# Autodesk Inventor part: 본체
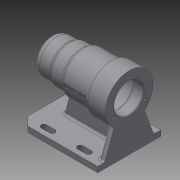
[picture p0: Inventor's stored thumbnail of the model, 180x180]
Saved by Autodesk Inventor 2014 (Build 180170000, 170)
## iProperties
Created: 2017-09
Part Number: 본체
Material: Generic
Document SubType Name: Modeling
Designer: user
Density: 1 g/cm^3
Appearance: Default
Author: user
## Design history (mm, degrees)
sketch "스케치1"
  geometry: L1 (0, 56)-(0, -56); L2 (21, -56)-(21, -41); L3 (21, -41)-(24, -41); L4 (24, -41)-(24, 13); L5 (24, 13)-(21, 13); L6 (21, 13)-(21, 25); L7 (21, 25)-(17.5, 25); L8 (17.5, 25)-(17.5, 43); L9 (17.5, 43)-(16, 43); L10 (16, 43)-(16, 47); L11 (16, 47)-(10.5, 47); L12 (10.5, 47)-(10.5, 50); L13 (25, 56)-(25, 31); L14 (25, 31)-(27, 31); L15 (27, 31)-(27, 11); L16 (27, 11)-(30, 11); L17 (30, 11)-(30, -28); L18 (30, -28)-(34, -28); L19 (34, -28)-(34, -56); L20 (34, -56)-(21, -56); L21 (25, 56)-(0, 56); L22 (10.5, 50)-(0, 50); L23 (0, 56)-(0, 50); 2 further points
  constraints: 46 end point, 6 perpendicular, 4 parallel, 2 point on line, 1 coincident, 1 collinear, 1 horizontal alignment, 1 midpoint, 1 vertical
  dimensions: "d0" = 112 distance of L1.start L1.end; "d1" = 42 diameter of L2 L1; "d2" = 48 diameter of L4 L1; "d3" = 15 distance of L2.start L2.end; "d4" = 54 distance of L3.end L4.end; "d5" = 42 diameter of L6 L1; "d6" = 12 distance of L5.end L6.end; "d7" = 18 distance of L7.end L8.end; "d8" = 35 diameter of L8 L1; "d9" = 32 diameter of L10 L1; "d11" = 4 distance of L9.end L10.end; "d13" = 3 distance of L11.end L12.end; "d14" = 21 diameter of L12 L1; "d20" = 60 diameter of L17 L1; "d21" = 54 diameter of L15 L1; "d22" = 50 diameter of L13 L1; "d23" = 68 diameter of L19 L1; "d24" = 112 distance between parallel lines of L20 L21; "d25" = 25 distance of L13.start L13.end; "d26" = 6 distance between parallel lines of L21 L22; "d28" = 3 distance of L2.end L3.end; "d29" = 3.5 distance of L6.end L7.end; "d30" = 1.5 distance of L8.end L9.end; "d32" = 45 distance from line of L15.end L21; "d33" = 84 distance between parallel lines of L18 L21
revolve "회전1" sketch "스케치1" stored, may be unused: angle "d27" = 90 deg
fillet "모깎기1" dims "d34" = 9
node "작업 평면1"
sketch "스케치2"
  geometry: L1 (-45, 56)-(45, 56); L2 (45, 56)-(45, -56); L3 (45, -56)-(-45, -56); L4 (-45, -56)-(-45, 56); L5 (-45, 56)-(45, -56); L6 (45, 56)-(-45, -56); 1 further point
  constraints: 12 end point, 2 midpoint, 2 parallel, 1 horizontal, 1 perpendicular
  dimensions: "d36" = 112 distance of L1.end L2.end; "d37" = 90 distance of L2.end L3.end
extrude "돌출1" join sketch "스케치2" distance "d38" = 8; taper "d39" = 0 deg
sketch "스케치3"
  geometry: C1 r 34 at (0, 0) reference; C2 r 21 at (0, 0) reference; A1 r 26 centre (0, 0) between (26, 0) and (-13, 22.517); 1 further point
  constraints: 3 point on circle, 1 centre point, 1 coincident, 1 horizontal alignment
  dimensions: "d40" = 52 diameter of A1; "d41" = 120 deg dimension on C1.centre A1.end A1.start; "d42" = 120 deg dimension on C1.centre point (-13, -22.517) A1.start
hole "구멍1" sketch "스케치3" at (26, 0), (-13, 22.517), (-13, -22.517) diameter "d43" = 3.242; stored, may be unused: countersink angle "d47" = 90 deg, drill point angle "d49" = 118 deg; dims "d44" = 8, "d45" = 4, "d46" = 2, "d48" = 11
sketch "스케치4"
  geometry: L1 (56, -45)-(56, 45) reference; L2 (56, 45)-(-56, 45) reference; L3 (-32, -34)-(-20, -34); L4 (-32, -38)-(-20, -38); L5 (-20, -30)-(-32, -30); L6 (20, -34)-(32, -34); L7 (20, -38)-(32, -38); L8 (32, -30)-(20, -30); L9 (-32, 34)-(-20, 34); L10 (-32, 30)-(-20, 30); L11 (-20, 38)-(-32, 38); L12 (20, 34)-(32, 34); L13 (20, 30)-(32, 30); L14 (32, 38)-(20, 38); A1 r 4 centre (-32, -34) between (-32, -30) and (-32, -38); A2 r 4 centre (-20, -34) between (-20, -38) and (-20, -30); A3 r 4 centre (20, -34) between (20, -30) and (20, -38); A4 r 4 centre (32, -34) between (32, -38) and (32, -30); A5 r 4 centre (-32, 34) between (-32, 38) and (-32, 30); A6 r 4 centre (-20, 34) between (-20, 30) and (-20, 38); A7 r 4 centre (20, 34) between (20, 38) and (20, 30); A8 r 4 centre (32, 34) between (32, 30) and (32, 38); 5 further points
  constraints: 32 end point, 16 point on circle, 16 tangent, 8 centre point, 8 parallel, 4 midpoint, 3 equal length, 1 horizontal alignment, 1 vertical alignment
  dimensions: "d50" = 34 vertical distance of point (0, 0) point (-26, 34); "d51" = 34 vertical distance of point (0, 0) point (-26, -34); "d52" = 4 radius of A5; "d53" = 4 radius of A8; "d54" = 4 radius of A4; "d55" = 4 radius of A2; "d56" = 12 distance of L9.end L9.start; "d57" = 40 distance of L12.start L9.end; "d58" = 40 distance of L6.start L3.end; "d59" = 24 distance from line of L1 L6.end; "d60" = 34 vertical distance of point (0, 0) point (26, 34)
extrude "돌출2" cut sketch "스케치4" stored distance "d61" = 8; taper "d62" = 0 deg
node "작업 평면2"
chamfer "모따기1" distance "d76" = 12; stored, may be unused: second distance "d77" = 2, angle "d78" = 45 deg
fillet "모깎기2" dims "d79" = 0.3
fillet "모깎기3" dims "d80" = 3
fillet "모깎기4" dims "d81" = 3
fillet "모깎기5" dims "d82" = 3
sketch "스케치7"
  geometry: L1 (-62, -56)-(-62, 44) reference; L2 (-27, 28.172)-(-27, 13.196) reference; L3 (-27, 24.622)-(-62, 34); L4 (-70, 56)-(-62, 56) reference; L5 (-62, 34)-(-62, -56); L6 (-34.002, -56)-(-62, -56); L7 (-34, -31)-(-34, -56) reference; 1 further point
  constraints: 6 end point, 2 perpendicular, 2 point on line
  dimensions: "d83" = 105 deg angle of L1 L3; "d84" = 22 distance from line of L4 L3.end; "d86" = 27.99839 distance of L6.start L1.start
feature "리브1" sketch "스케치7" dims "d87" = 1, "d88" = 8, "d89" = 0, "d90" = 0, "d91" = 1, "d92" = 1
sketch "스케치8"
  geometry: L1 (8, 41)-(8, 0) reference; L2 (8, 41)-(36.236, 41) reference; L3 (36.236, 49)-(8, 49) reference; L4 (8, 90)-(8, 49) reference; L5 (43.992, 66.9)-(8, 80); L6 (43.992, 23.1)-(8, 10); A1 r 34 centre (70, 45) between (36.236, 41) and (36.236, 49) reference
  constraints: 4 end point, 2 point on circle, 2 point on line, 1 equal length
  dimensions: "d93" = 110 deg angle of L5 L4; "d94" = 10 distance of L4.start L5.end; "d95" = 110 deg angle of L1 L6
extrude "돌출5" join sketch "스케치8" distance "d96" = 8; taper "d97" = 0 deg
fillet "모깎기6" dims "d98" = 3
fillet "모깎기7" dims "d99" = 3
chamfer "모따기2" distance "d100" = 1; stored, may be unused: second distance "d101" = 2, angle "d102" = 45 deg
node "작업 평면3"
sketch "스케치9"
  geometry: L1 (-26.008, -56)-(34, -56) reference; L2 (-70, 44)-(-70, -56) reference; 2 further points
  constraints: 1 other
  dimensions: "d104" = 48 distance from line of L1 point (0, -8); "d105" = 70 distance from line of L2 point (0, -8)
feature "엠보싱1" sketch "스케치9" dims "d106" = 0.5, "d107" = 0
node "솔리드1"
other parameters: "d103" = 35
